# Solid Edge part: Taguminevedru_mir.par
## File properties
Author: Türk
Template: Iso Part.par
Last saved by: Türk
Revision: 2
Application: Solid Edge
Accuracy: 0,990
Username: Türk
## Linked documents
Taguminevedru.par
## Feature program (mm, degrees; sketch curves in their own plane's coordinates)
part copy "CopiedPart_1"
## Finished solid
Body 1: solid body, 7 faces, 18 edges, 12 vertices.
  Faces by surface: plane 4, torus 2, spline 1
  Edges by curve: circle 10, intersection 6, line 2
Bounding box of the edges (mm; curved faces can reach further): 103.000 x 229.400 x 103.000, from (-51.5, -229.4, -51.5) to (51.5, 0, 51.5).
Toroidal faces (ring radius, tube radius in mm): R45.5 r6 x2
Planar faces by outward normal: +y 1, -y 1, oblique 2
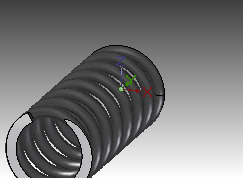
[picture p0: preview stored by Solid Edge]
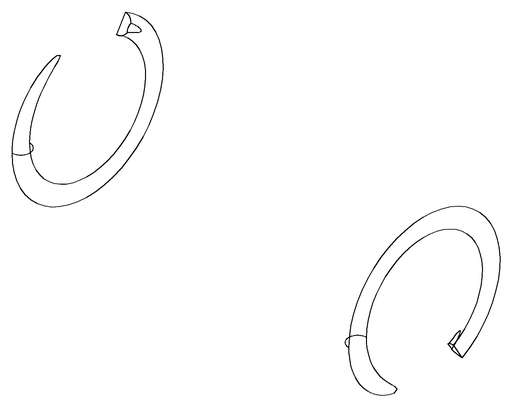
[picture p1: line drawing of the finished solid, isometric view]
